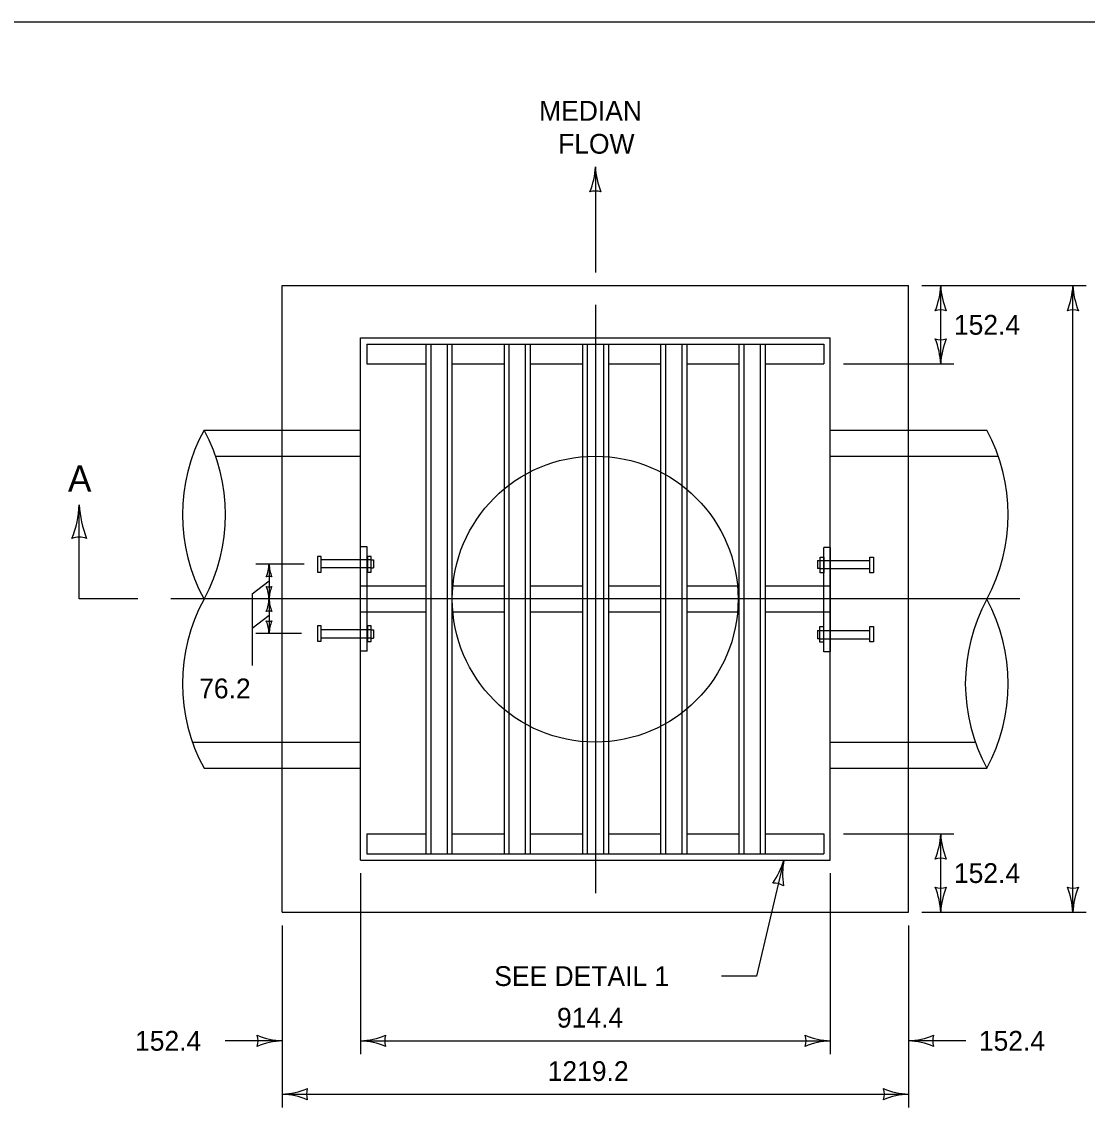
# Model space of a CAD drawing. Extents: x 49991.4 to 50021, y 49987.6 to 50011.4.
# Drawn here: x 50008.404 to 50011.636, y 49995.684 to 49998.999 of the extents above; entities that cross this region are included whole.
import ezdxf

# ---------------------------------------------------------------- set-up
doc = ezdxf.new("R2010")
doc.units = 0
for name, color, linetype in [('Level 1', 7, 'Continuous'), ('Level 2', 7, 'Continuous'), ('Level 3', 7, 'Continuous'), ('Level 4', 7, 'Continuous'), ('Level 5', 7, 'Continuous'), ('Level 6', 7, 'Continuous')]:
    doc.layers.add(name, color=color, linetype=linetype)

msp = doc.modelspace()

# ---------------------------------------------------------------- linework, layer by layer
at = {"layer": 'Level 1'}
for p, q in [((50009.1943, 49998.1994), (50011.0943, 49998.1994)), ((50009.1943, 49997.3764), (50009.1943, 49998.1994)), ((50009.1943, 49998.1994), (50011.0943, 49998.1994)), ((50011.0943, 49996.2993), (50011.0943, 49998.1994)), ((50009.4318, 49996.4576), (50009.4318, 49998.041)), ((50009.4318, 49998.041), (50010.8568, 49998.041)), ((50010.8568, 49996.4576), (50010.8568, 49998.041)), ((50009.4508, 49998.022), (50010.8378, 49998.022)), ((50009.4508, 49998.022), (50009.4508, 49997.9619)), ((50009.6297, 49998.022), (50009.6297, 49997.21)), ((50009.7089, 49998.022), (50009.7089, 49996.4766)), ((50009.8672, 49998.022), (50009.8672, 49996.4766)), ((50009.9464, 49998.022), (50009.9464, 49996.4766)), ((50010.1047, 49998.022), (50010.1047, 49996.4766)), ((50010.1839, 49998.022), (50010.1839, 49996.4766)), ((50010.3422, 49998.022), (50010.3422, 49997.2049)), ((50010.4214, 49998.022), (50010.4214, 49996.4766)), ((50010.5797, 49998.022), (50010.5797, 49996.4766)), ((50010.6589, 49998.022), (50010.6589, 49996.4766)), ((50010.8378, 49998.022), (50010.8378, 49997.9619)), ((50009.4508, 49997.9619), (50009.6297, 49997.9619)), ((50009.7089, 49997.9619), (50009.8672, 49997.9619)), ((50009.9464, 49997.9619), (50010.1047, 49997.9619)), ((50010.1839, 49997.9619), (50010.3422, 49997.9619)), ((50010.4214, 49997.9619), (50010.5797, 49997.9619)), ((50010.6589, 49997.9619), (50010.8378, 49997.9619)), ((50011.0943, 49997.7614), (50011.3318, 49997.7614)), ((50009.4318, 49997.2494), (50009.4318, 49997.4077)), ((50009.4517, 49997.4077), (50009.4318, 49997.4077)), ((50009.4517, 49997.2494), (50009.4517, 49997.4077)), ((50010.8378, 49997.2472), (50010.8378, 49997.4055)), ((50010.8576, 49997.4055), (50010.8378, 49997.4055)), ((50010.8576, 49997.2472), (50010.8576, 49997.4055)), ((50009.1943, 49997.0801), (50009.1943, 49997.3764)), ((50009.4637, 49997.3681), (50009.4714, 49997.3681)), ((50009.4714, 49997.3681), (50009.4714, 49997.3434)), ((50010.818, 49997.3659), (50010.818, 49997.3412)), ((50010.818, 49997.3659), (50010.8258, 49997.3659)), ((50009.4637, 49997.3434), (50009.4714, 49997.3434)), ((50010.8258, 49997.3412), (50010.818, 49997.3412)), ((50009.4318, 49997.2889), (50009.6297, 49997.2889)), ((50009.7089, 49997.2889), (50009.8672, 49997.2889)), ((50009.9467, 49997.2889), (50010.1047, 49997.2889)), ((50010.1839, 49997.2889), (50010.3422, 49997.2889)), ((50010.4214, 49997.2889), (50010.5797, 49997.2889)), ((50010.6589, 49997.2889), (50010.8568, 49997.2889)), ((50009.4318, 49997.091), (50009.4318, 49997.2494)), ((50009.4517, 49997.091), (50009.4517, 49997.2494)), ((50010.8378, 49997.0889), (50010.8378, 49997.2472)), ((50010.8576, 49997.0889), (50010.8576, 49997.2472)), ((50009.4318, 49997.2098), (50009.6297, 49997.2098)), ((50009.6297, 49997.2098), (50009.6297, 49996.4766)), ((50009.7089, 49997.2098), (50009.8672, 49997.2098)), ((50009.9464, 49997.2098), (50010.1047, 49997.2098)), ((50010.1839, 49997.2098), (50010.3422, 49997.2098)), ((50010.3422, 49997.2098), (50010.3422, 49996.4766)), ((50010.4214, 49997.2098), (50010.5797, 49997.2098)), ((50010.6589, 49997.2098), (50010.8568, 49997.2098)), ((50009.4642, 49997.1554), (50009.4714, 49997.1554)), ((50009.4714, 49997.1554), (50009.4714, 49997.1306)), ((50010.818, 49997.1532), (50010.818, 49997.1284)), ((50010.818, 49997.1532), (50010.8252, 49997.1532)), ((50009.4642, 49997.1306), (50009.4714, 49997.1306)), ((50010.8252, 49997.1284), (50010.818, 49997.1284)), ((50009.1943, 49996.2993), (50009.1943, 49997.0801)), ((50009.4517, 49997.091), (50009.4318, 49997.091)), ((50010.8576, 49997.0889), (50010.8378, 49997.0889)), ((50011.0943, 49996.7359), (50011.3318, 49996.7359)), ((50009.4508, 49996.5368), (50009.6297, 49996.5368)), ((50009.4508, 49996.5368), (50009.4508, 49996.4766)), ((50009.7089, 49996.5368), (50009.8672, 49996.5368)), ((50009.9464, 49996.5368), (50010.1047, 49996.5368)), ((50010.1839, 49996.5368), (50010.3422, 49996.5368)), ((50010.4214, 49996.5368), (50010.5797, 49996.5368)), ((50010.6589, 49996.5368), (50010.8378, 49996.5368)), ((50010.8378, 49996.5368), (50010.8378, 49996.4766)), ((50009.4508, 49996.4766), (50010.8378, 49996.4766)), ((50009.4318, 49996.4576), (50010.8568, 49996.4576)), ((50009.1943, 49996.2993), (50011.0943, 49996.2993))]:
    msp.add_line(p, q, dxfattribs=at)
for points in [[(49999.3835, 49998.9992), (50016.7501, 49998.9992), (50016.7501, 49987.7988), (49999.3835, 49987.7988)], [(50009.4524, 49997.3779), (50009.4524, 49997.3309), (50009.4637, 49997.3309), (50009.4637, 49997.3779)], [(50010.8369, 49997.3757), (50010.8369, 49997.3286), (50010.8258, 49997.3286), (50010.8258, 49997.3757)], [(50009.453, 49997.1679), (50009.453, 49997.1207), (50009.4642, 49997.1207), (50009.4642, 49997.1679)], [(50010.8364, 49997.1656), (50010.8364, 49997.1186), (50010.8252, 49997.1186), (50010.8252, 49997.1656)]]:
    msp.add_lwpolyline(points, close=True, dxfattribs=at)
for centre, start_param, end_param in [((50010.8603, 49997.505), 1.072803, 2.06879), ((50011.8033, 49996.9923), 4.214396, 5.210382), ((50010.8603, 49996.9923), 1.072803, 2.06879)]:
    msp.add_ellipse(centre, major_axis=(0, -0.5367), ratio=0.99996, start_param=start_param, end_param=end_param, dxfattribs=at)
at = {"layer": 'Level 3'}
for p, q in [((50010.1443, 49998.5595), (50010.1443, 49998.2394)), ((50011.1343, 49998.1994), (50011.6329, 49998.1994)), ((50011.192, 49997.9619), (50011.192, 49998.1994)), ((50011.5929, 49996.2993), (50011.5929, 49998.1994)), ((50010.8968, 49997.9619), (50011.232, 49997.9619)), ((50009.2609, 49997.3544), (50009.1143, 49997.3544)), ((50009.1543, 49997.3544), (50009.1543, 49997.2494)), ((50009.1028, 49997.2652), (50009.1543, 49997.3039)), ((50009.1028, 49997.2652), (50009.1028, 49997.048)), ((50009.1543, 49997.2494), (50009.1543, 49997.1448)), ((50009.1028, 49997.1611), (50009.1543, 49997.1998)), ((50009.2527, 49997.1448), (50009.1143, 49997.1448)), ((50010.8968, 49996.5368), (50011.232, 49996.5368)), ((50011.192, 49996.2993), (50011.192, 49996.5368)), ((50010.716, 49996.4576), (50010.6333, 49996.1057)), ((50009.4318, 49996.4176), (50009.4318, 49995.8695)), ((50010.8568, 49996.4176), (50010.8568, 49995.8695)), ((50011.1343, 49996.2993), (50011.6329, 49996.2993)), ((50009.1943, 49996.2593), (50009.1943, 49995.7077)), ((50009.1943, 49996.2493), (50009.1943, 49995.881)), ((50011.0943, 49996.2593), (50011.0943, 49995.7077)), ((50010.6333, 49996.1057), (50010.5268, 49996.1057)), ((50009.1943, 49995.9095), (50009.0209, 49995.9095)), ((50009.4318, 49995.9095), (50010.8568, 49995.9095)), ((50011.2677, 49995.9095), (50011.0943, 49995.9095)), ((50009.1943, 49995.7477), (50011.0943, 49995.7477))]:
    msp.add_line(p, q, dxfattribs=at)
for centre, radius, start, end in [((50010.9699, 49998.2086), 0.2223, 337.456, 357.6395), ((50011.4247, 49998.2109), 0.233, 182.8273, 202.0772), ((50011.192, 49998.0712), 0.0548, 72.1388, 107.8612), ((50011.192, 49998.0901), 0.0548, 252.1388, 287.8612), ((50010.9593, 49997.9504), 0.233, 2.8273, 22.0772), ((50011.4141, 49997.9527), 0.2223, 157.456, 177.6395), ((50009.0432, 49997.359), 0.1112, 337.456, 357.6395), ((50009.2707, 49997.3601), 0.1165, 182.8273, 202.0772), ((50009.1543, 49997.2903), 0.0274, 72.1388, 107.8612), ((50009.1543, 49997.3135), 0.0274, 252.1388, 287.8612), ((50009.0379, 49997.2437), 0.1165, 2.8273, 22.0772), ((50009.2654, 49997.2448), 0.1112, 157.456, 177.6395), ((50009.0432, 49997.254), 0.1112, 337.456, 357.6395), ((50009.2707, 49997.2551), 0.1165, 182.8273, 202.0772), ((50009.1543, 49997.1853), 0.0274, 72.1388, 107.8612), ((50009.1543, 49997.2089), 0.0274, 252.1388, 287.8612), ((50009.0379, 49997.1391), 0.1165, 2.8273, 22.0772), ((50009.2654, 49997.1402), 0.1112, 157.456, 177.6395), ((50010.9699, 49996.546), 0.2223, 337.456, 357.6395), ((50011.4247, 49996.5483), 0.233, 182.8273, 202.0772), ((50011.192, 49996.4086), 0.0548, 72.1388, 107.8612), ((50011.192, 49996.4275), 0.0548, 252.1388, 287.8612), ((50010.9593, 49996.2878), 0.233, 2.8273, 22.0772), ((50011.4141, 49996.2901), 0.2223, 157.456, 177.6395), ((50009.2035, 49996.1316), 0.2223, 247.456, 267.6395), ((50009.0661, 49995.9095), 0.0548, 342.1388, 17.8612), ((50009.2058, 49995.6768), 0.233, 92.8273, 112.0772), ((50011.0828, 49996.1422), 0.233, 272.8273, 292.0772), ((50011.0851, 49995.6874), 0.2223, 67.456, 87.6395), ((50011.2225, 49995.9095), 0.0548, 162.1388, 197.8612), ((50009.1828, 49995.9804), 0.233, 272.8273, 292.0772), ((50009.1851, 49995.5256), 0.2223, 67.456, 87.6395), ((50009.3225, 49995.7477), 0.0548, 162.1388, 197.8612), ((50011.1035, 49995.9698), 0.2223, 247.456, 267.6395), ((50010.9661, 49995.7477), 0.0548, 342.1388, 17.8612), ((50011.1058, 49995.515), 0.233, 92.8273, 112.0772)]:
    msp.add_arc(centre, radius, start, end, dxfattribs=at)
for centre, major_axis, start_param, end_param in [((50009.9222, 49998.5687), (0, -0.2223), 1.177329, 1.529598), ((50009.9222, 49998.5686), (0, -0.2223), 1.177329, 1.529598), ((50010.377, 49998.571), (0, -0.233), 4.761735, 5.097708), ((50010.377, 49998.571), (0, -0.233), 4.761735, 5.097708), ((50010.1443, 49998.4313), (0, 0.0548), 5.971449, 6.594922), ((50010.1443, 49998.4312), (0, 0.0548), 5.971449, 6.594922), ((50011.3708, 49998.2086), (0, -0.2223), 1.177329, 1.529598), ((50011.8256, 49998.2109), (0, -0.233), 4.761735, 5.097708), ((50011.5929, 49998.0712), (0, 0.0548), 5.971449, 6.594922), ((50008.2822, 49997.5466), (0, -0.2964), 1.177329, 1.529598), ((50008.8887, 49997.5497), (0, -0.3107), 4.761735, 5.097708), ((50008.5784, 49997.3634), (0, 0.073), 5.971449, 6.594922), ((50010.5018, 49996.5173), (0, -0.2223), 0.946632, 1.2989), ((50010.9452, 49996.4156), (0, 0.233), 1.389444, 1.725418), ((50010.6867, 49996.3328), (0, 0.0548), 5.740751, 6.364224), ((50011.5929, 49996.4275), (0, -0.0548), 5.971449, 6.594922), ((50011.3602, 49996.2878), (0, 0.233), 4.761735, 5.097708), ((50011.815, 49996.2901), (0, 0.2223), 1.177329, 1.529598), ((50009.4203, 49996.1422), (0, -0.233), 0.049346, 0.385319), ((50009.4226, 49995.6874), (0, 0.2223), 5.889718, 6.241987), ((50009.56, 49995.9095), (0, 0.0548), 1.25906, 1.882533), ((50010.866, 49996.1316), (0, -0.2223), 5.889718, 6.241987), ((50010.7286, 49995.9095), (0, -0.0548), 1.25906, 1.882533), ((50010.8683, 49995.6768), (0, 0.233), 0.049346, 0.385319)]:
    msp.add_ellipse(centre, major_axis=major_axis, ratio=0.99996, start_param=start_param, end_param=end_param, dxfattribs=at)
at = {"layer": 'Level 4'}
for p, q in [((50009.6447, 49998.022), (50009.6447, 49996.4766)), ((50009.6941, 49998.022), (50009.6941, 49996.4766)), ((50009.8821, 49998.022), (50009.8821, 49996.4766)), ((50009.9316, 49998.022), (50009.9316, 49996.4766)), ((50010.1196, 49998.022), (50010.1196, 49996.4766)), ((50010.1691, 49998.022), (50010.1691, 49996.4766)), ((50010.3571, 49998.022), (50010.3571, 49996.4766)), ((50010.4065, 49998.022), (50010.4065, 49996.4766)), ((50010.5946, 49998.022), (50010.5946, 49996.4766)), ((50010.644, 49998.022), (50010.644, 49996.4766)), ((50008.9569, 49997.7614), (50009.1943, 49997.7614)), ((50009.1943, 49997.7614), (50009.4318, 49997.7614)), ((50010.8568, 49997.7614), (50011.0943, 49997.7614)), ((50008.9919, 49997.6823), (50009.4318, 49997.6823)), ((50010.8568, 49997.6823), (50011.3669, 49997.6823)), ((50009.4637, 49997.3681), (50009.3131, 49997.3681)), ((50010.8258, 49997.3659), (50010.9764, 49997.3659)), ((50009.4637, 49997.3434), (50009.3131, 49997.3434)), ((50010.8258, 49997.3412), (50010.9764, 49997.3412)), ((50009.4642, 49997.1554), (50009.3131, 49997.1554)), ((50010.8252, 49997.1532), (50010.9764, 49997.1532)), ((50009.4642, 49997.1306), (50009.3131, 49997.1306)), ((50010.8252, 49997.1284), (50010.9764, 49997.1284)), ((50008.9218, 49996.815), (50009.4318, 49996.815)), ((50010.8568, 49996.815), (50011.2968, 49996.815)), ((50008.9569, 49996.7359), (50009.1943, 49996.7359)), ((50009.1943, 49996.7359), (50009.4318, 49996.7359)), ((50010.8568, 49996.7359), (50011.0943, 49996.7359))]:
    msp.add_line(p, q, dxfattribs=at)
for points in [[(50009.3015, 49997.3779), (50009.3015, 49997.3309), (50009.3127, 49997.3309), (50009.3127, 49997.3779)], [(50010.988, 49997.3757), (50010.988, 49997.3286), (50010.9768, 49997.3286), (50010.9768, 49997.3757)], [(50009.3015, 49997.1683), (50009.3015, 49997.1213), (50009.3127, 49997.1213), (50009.3127, 49997.1683)], [(50010.988, 49997.1662), (50010.988, 49997.119), (50010.9768, 49997.119), (50010.9768, 49997.1662)]]:
    msp.add_lwpolyline(points, close=True, dxfattribs=at)
for centre, start_param, end_param in [((50009.4284, 49997.505), 4.214396, 5.210382), ((50008.4854, 49997.505), 1.072803, 2.06879), ((50009.4284, 49996.9923), 4.214396, 5.210382)]:
    msp.add_ellipse(centre, major_axis=(0, -0.5367), ratio=0.99996, start_param=start_param, end_param=end_param, dxfattribs=at)
msp.add_ellipse((50010.1438, 49997.2487), major_axis=(0, 0.4336), ratio=0.99996, dxfattribs=at)
at = {"layer": 'Level 5'}
for p, q in [((50010.1443, 49998.141), (50010.1443, 49996.3576)), ((50011.4322, 49997.2494), (50008.8565, 49997.2494))]:
    msp.add_line(p, q, dxfattribs=at)
at = {"layer": 'Level 6'}
for p, q in [((50008.5784, 49997.2494), (50008.5784, 49997.5344)), ((50008.7565, 49997.2494), (50008.5784, 49997.2494))]:
    msp.add_line(p, q, dxfattribs=at)

# ---------------------------------------------------------------- texts
at = {"layer": 'Level 2'}
for s, height, p in [('MEDIAN', 0.06, (50009.9736, 49998.6995)), ('FLOW', 0.06, (50010.0312, 49998.5995)), ('152.4', 0.06, (50011.232, 49998.0506)), ('A', 0.08, (50008.5441, 49997.5744)), ('76.2', 0.06, (50008.9422, 49996.948)), ('152.4', 0.06, (50011.232, 49996.3881)), ('SEE DETAIL 1', 0.059999, (50009.8375, 49996.0757)), ('914.4', 0.06, (50010.0277, 49995.9495)), ('152.4', 0.06, (50008.7477, 49995.8795)), ('152.4', 0.06, (50011.3077, 49995.8795)), ('1219.2', 0.06, (50009.9996, 49995.7877))]:
    msp.add_text(s, height=height, dxfattribs=at).set_placement(p)

doc.saveas('drawing.dxf')
